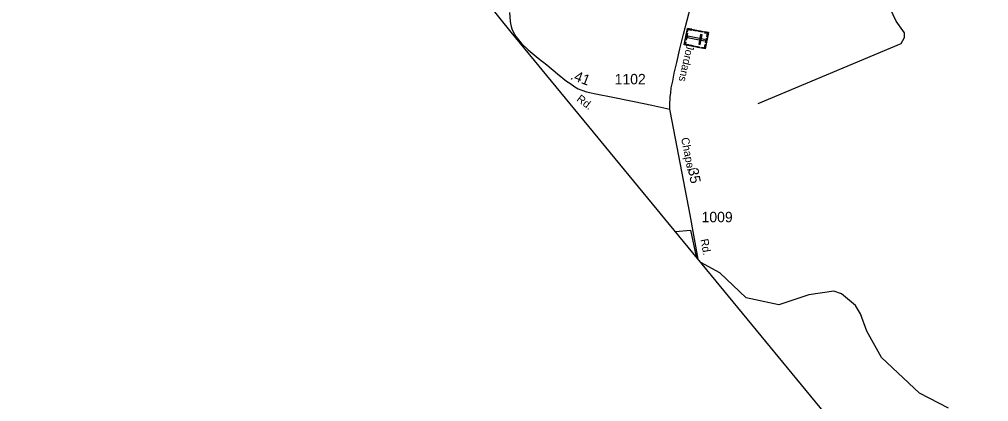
# Model space of a CAD drawing. Extents: x 2206922 to 2357709, y 510027 to 673830.
# Drawn here: x 2212909 to 2224516, y 541278 to 545864 of the extents above; entities that cross this region are included whole.
import ezdxf

# ---------------------------------------------------------------- set-up
doc = ezdxf.new("R2010")
doc.units = 0
for name, color, linetype in [('Exist Boundary Political CountyLine', 7, 'Continuous'), ('Exist Cultural Cemetery CELL', 7, 'Continuous'), ('Exist Hydrographic Creek Single Shore', 7, 'Continuous'), ('Exist Hydrographic Misc Water Feature', 7, 'Continuous'), ('Exist Road Secondary Mileage Hundredths English Label', 7, 'Continuous'), ('Exist Road Secondary Type 51 Attributed', 7, 'Continuous'), ('Exist Road Secondary Type 51 Label', 7, 'Continuous'), ('Exist Road Secondary Type 51 Number Label', 7, 'Continuous')]:
    doc.layers.add(name, color=color, linetype=linetype)

msp = doc.modelspace()

# ---------------------------------------------------------------- linework, layer by layer
at = {"layer": 'Exist Boundary Political CountyLine'}
msp.add_lwpolyline([(2225101, 538040), (2218799, 545711), (2217828, 546923), (2217376, 547429), (2215140, 550249), (2214180, 551436), (2213926, 551742), (2212977, 552913), (2212501, 553514), (2212251, 553818), (2211999, 554136), (2211771, 554406), (2211519, 554714), (2211295, 554997), (2210995, 555354), (2210793, 555609), (2209571, 557124), (2209107, 557689), (2208629, 558275), (2208129, 558903), (2207662, 559468), (2207422, 559770), (2206922, 560323)], dxfattribs=at)
at = {"layer": 'Exist Cultural Cemetery CELL'}
for points in [[(2221160, 545705), (2221121, 545510), (2220871, 545560), (2220910, 545755)], [(2220910, 545697), (2220893, 545613), (2220882, 545616), (2220899, 545699)], [(2220904, 545723), (2220915, 545720), (2220919, 545742), (2220959, 545734), (2220961, 545745), (2220910, 545755)], [(2220979, 545741), (2221021, 545733), (2221019, 545722), (2220976, 545730)], [(2221045, 545728), (2221087, 545720), (2221085, 545709), (2221042, 545717)], [(2221085, 545678), (2221067, 545682), (2221044, 545567), (2221062, 545563)], [(2221117, 545714), (2221115, 545703), (2221147, 545696), (2221139, 545656), (2221150, 545654), (2221160, 545705)], [(2220878, 545592), (2220889, 545590), (2220884, 545569), (2220924, 545561), (2220922, 545550), (2220871, 545560)], [(2221110, 545604), (2221113, 545622), (2220914, 545662), (2220911, 545644)], [(2220944, 545557), (2220987, 545548), (2220984, 545537), (2220942, 545546)], [(2221078, 545518), (2221080, 545530), (2221112, 545523), (2221120, 545563), (2221131, 545561), (2221121, 545510)], [(2221145, 545633), (2221135, 545582), (2221124, 545584), (2221134, 545635)], [(2221009, 545544), (2221051, 545535), (2221049, 545524), (2221007, 545533)]]:
    msp.add_lwpolyline(points, close=True, dxfattribs=at)
at = {"layer": 'Exist Hydrographic Creek Single Shore'}
msp.add_lwpolyline([(2224034, 541199), (2223688, 541380), (2223235, 541809), (2223058, 542124), (2222982, 542332), (2222923, 542432), (2222755, 542573), (2222663, 542605), (2222364, 542561), (2222005, 542441), (2221611, 542524), (2221299, 542823), (2221069, 542948)], dxfattribs=at)
at = {"layer": 'Exist Hydrographic Misc Water Feature'}
for points in [[(2221757, 544856), (2223468, 545576), (2223509, 545644), (2223508, 545700), (2223408, 545843), (2223124, 546445), (2222400, 546808)], [(2220765, 543319), (2220947, 543337), (2221013, 543017)]]:
    msp.add_lwpolyline(points, dxfattribs=at)
at = {"layer": 'Exist Road Secondary Type 51 Attributed'}
for points in [[(2220700, 544786), (2220700, 544857), (2220702, 544912), (2220703, 544939), (2220709, 544980), (2220716, 545044), (2220733, 545124), (2220751, 545219), (2220782, 545348), (2220820, 545511), (2220861, 545684), (2220951, 546021), (2221013, 546224), (2221188, 546726), (2221262, 546935), (2221290, 547019), (2221307, 547081)], [(2218780, 545946), (2218788, 545840), (2218791, 545812), (2218798, 545777), (2218808, 545751), (2218824, 545712)], [(2218824, 545712), (2218856, 545658), (2218887, 545619), (2218923, 545574), (2219001, 545500), (2219121, 545398), (2219224, 545320), (2219353, 545209), (2219463, 545123), (2219501, 545097), (2219562, 545055), (2219602, 545032), (2219645, 545014), (2219702, 544996), (2219758, 544981), (2219792, 544975), (2219851, 544962), (2219977, 544938), (2220270, 544878), (2220482, 544834), (2220700, 544786)], [(2221038, 542987), (2220941, 543517), (2220708, 544745), (2220700, 544786)]]:
    msp.add_lwpolyline(points, dxfattribs=at)

# ---------------------------------------------------------------- texts
at = {"layer": 'Exist Road Secondary Mileage Hundredths English Label'}
for s, rotation, p in [('.41', 338.9527, (2219498, 545150)), ('.35', 280.7856, (2220906, 544114))]:
    msp.add_text(s, height=125, rotation=rotation, dxfattribs=at).set_placement(p)
at = {"layer": 'Exist Road Secondary Type 51 Label'}
for s, rotation, p in [('Jordans', 257.3392, (2220902, 545569)), ('Rd.', 322.3164, (2219574, 544893)), ('Chapel', 280.7856, (2220833, 544438)), ('Rd.', 280.7856, (2221064, 543222))]:
    msp.add_text(s, height=95, rotation=rotation, dxfattribs=at).set_placement(p)
at = {"layer": 'Exist Road Secondary Type 51 Number Label'}
for s, p in [('1102', (2220038, 545084)), ('1009', (2221079, 543430))]:
    msp.add_text(s, height=125, dxfattribs=at).set_placement(p)

doc.saveas('drawing.dxf')
